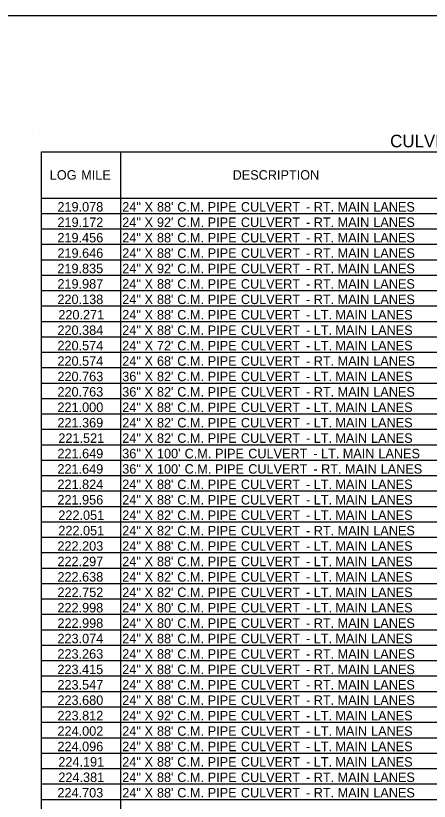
# Model space of a CAD drawing. Extents: x 2261867 to 2275370, y -3124789 to -3122260.
# Drawn here: x 2265138.2 to 2265400.1, y -3124272.1 to -3123775.3 of the extents above; entities that cross this region are included whole.
import ezdxf

# ---------------------------------------------------------------- set-up
doc = ezdxf.new("R2010")
doc.units = 0
for name, color, linetype in [('Default', 7, 'Continuous'), ('DSN_DRFT_Named-Boundary', 7, 'Continuous'), ('DSN_QNTY_Annotation', 7, 'Continuous')]:
    doc.layers.add(name, color=color, linetype=linetype)

msp = doc.modelspace()

# ---------------------------------------------------------------- linework, layer by layer
at = {"layer": 'Default'}
msp.add_line((2265148.63, -3123847.74), (2265148.63, -3123847.74), dxfattribs=at)
at = {"layer": 'DSN_DRFT_Named-Boundary'}
msp.add_lwpolyline([(2264290.05, -3124774.39), (2265915.05, -3124774.39), (2265915.05, -3123775.33), (2264290.05, -3123775.33)], close=True, dxfattribs=at)
at = {"layer": 'DSN_QNTY_Annotation'}
for p, q in [((2265154.48, -3123861.39), (2265745.33, -3123861.39)), ((2265154.48, -3124516.11), (2265154.48, -3123861.39)), ((2265154.48, -3124516.11), (2265154.48, -3123861.39)), ((2265204.69, -3124505.38), (2265204.69, -3123861.39)), ((2265154.48, -3123890.64), (2265745.33, -3123890.64)), ((2265204.69, -3124505.38), (2265204.69, -3123890.64)), ((2265154.48, -3123900.39), (2265745.33, -3123900.39)), ((2265154.48, -3123910.14), (2265745.33, -3123910.14)), ((2265154.48, -3123919.89), (2265745.33, -3123919.89)), ((2265154.48, -3123929.64), (2265745.33, -3123929.64)), ((2265154.48, -3123939.39), (2265745.33, -3123939.39)), ((2265154.48, -3123949.14), (2265745.33, -3123949.14)), ((2265154.48, -3123958.89), (2265745.33, -3123958.89)), ((2265154.48, -3123968.64), (2265745.33, -3123968.64)), ((2265154.48, -3123978.39), (2265745.33, -3123978.39)), ((2265154.48, -3123988.14), (2265745.33, -3123988.14)), ((2265154.48, -3123997.89), (2265745.33, -3123997.89)), ((2265154.48, -3124007.64), (2265745.33, -3124007.64)), ((2265154.48, -3124017.39), (2265745.33, -3124017.39)), ((2265154.48, -3124027.14), (2265745.33, -3124027.14)), ((2265154.48, -3124036.89), (2265745.33, -3124036.89)), ((2265154.48, -3124046.64), (2265745.33, -3124046.64)), ((2265154.48, -3124056.39), (2265745.33, -3124056.39)), ((2265154.48, -3124066.14), (2265745.33, -3124066.14)), ((2265154.48, -3124075.89), (2265745.33, -3124075.89)), ((2265154.48, -3124085.64), (2265745.33, -3124085.64)), ((2265154.48, -3124095.39), (2265745.33, -3124095.39)), ((2265154.48, -3124105.14), (2265745.33, -3124105.14)), ((2265154.48, -3124114.89), (2265745.33, -3124114.89)), ((2265154.48, -3124124.64), (2265745.33, -3124124.64)), ((2265154.48, -3124134.39), (2265745.33, -3124134.39)), ((2265154.48, -3124144.14), (2265745.33, -3124144.14)), ((2265154.48, -3124153.89), (2265745.33, -3124153.89)), ((2265154.48, -3124163.64), (2265745.33, -3124163.64)), ((2265154.48, -3124173.39), (2265745.33, -3124173.39)), ((2265154.48, -3124183.14), (2265745.33, -3124183.14)), ((2265154.48, -3124192.89), (2265745.33, -3124192.89)), ((2265154.48, -3124202.64), (2265745.33, -3124202.64)), ((2265154.48, -3124212.39), (2265745.33, -3124212.39)), ((2265154.48, -3124222.14), (2265745.33, -3124222.14)), ((2265154.48, -3124231.89), (2265745.33, -3124231.89)), ((2265154.48, -3124241.64), (2265745.33, -3124241.64)), ((2265154.48, -3124251.39), (2265745.33, -3124251.39)), ((2265154.48, -3124261.14), (2265745.33, -3124261.14)), ((2265154.48, -3124270.89), (2265745.33, -3124270.89))]:
    msp.add_line(p, q, dxfattribs=at)

# ---------------------------------------------------------------- texts
for s, height, p in [('CULVERT', 8, (2265375.32, -3123858.57)), ('LOG', 6, (2265159.79, -3123879.02)), (' MILE', 6, (2265177.44, -3123879.02)), ('DESCRIPTION', 6, (2265275.58, -3123879.02)), ('219.078', 6, (2265164.63, -3123899.19)), ('24"', 6, (2265205.67, -3123899.19)), (' X', 6, (2265217.57, -3123899.19)), (" 88'", 6, (2265225.44, -3123899.19)), (' C.M.', 6, (2265238.29, -3123899.19)), (' PIPE', 6, (2265257.58, -3123899.19)), (' CULVERT', 6, (2265278.57, -3123899.19)), (' -', 6, (2265319.86, -3123899.19)), (' RT.', 6, (2265324.71, -3123899.19)), (' MAIN', 6, (2265339.82, -3123899.19)), (' LANES', 6, (2265362.42, -3123899.19)), ('219.172', 6, (2265164.66, -3123908.94)), ('24"', 6, (2265205.67, -3123908.94)), (' X', 6, (2265217.57, -3123908.94)), (" 92'", 6, (2265225.44, -3123908.94)), (' C.M.', 6, (2265238.29, -3123908.94)), (' PIPE', 6, (2265257.58, -3123908.94)), (' CULVERT', 6, (2265278.57, -3123908.94)), (' -', 6, (2265319.86, -3123908.94)), (' RT.', 6, (2265324.71, -3123908.94)), (' MAIN', 6, (2265339.82, -3123908.94)), (' LANES', 6, (2265362.42, -3123908.94)), ('219.456', 6, (2265164.63, -3123918.69)), ('24"', 6, (2265205.67, -3123918.69)), (' X', 6, (2265217.57, -3123918.69)), (" 88'", 6, (2265225.44, -3123918.69)), (' C.M.', 6, (2265238.29, -3123918.69)), (' PIPE', 6, (2265257.58, -3123918.69)), (' CULVERT', 6, (2265278.57, -3123918.69)), (' -', 6, (2265319.86, -3123918.69)), (' RT.', 6, (2265324.71, -3123918.69)), (' MAIN', 6, (2265339.82, -3123918.69)), (' LANES', 6, (2265362.42, -3123918.69)), ('219.646', 6, (2265164.63, -3123928.44)), ('24"', 6, (2265205.67, -3123928.44)), (' X', 6, (2265217.57, -3123928.44)), (" 88'", 6, (2265225.44, -3123928.44)), (' C.M.', 6, (2265238.29, -3123928.44)), (' PIPE', 6, (2265257.58, -3123928.44)), (' CULVERT', 6, (2265278.57, -3123928.44)), (' -', 6, (2265319.86, -3123928.44)), (' RT.', 6, (2265324.71, -3123928.44)), (' MAIN', 6, (2265339.82, -3123928.44)), (' LANES', 6, (2265362.42, -3123928.44)), ('219.835', 6, (2265164.61, -3123938.19)), ('24"', 6, (2265205.67, -3123938.19)), (' X', 6, (2265217.57, -3123938.19)), (" 92'", 6, (2265225.44, -3123938.19)), (' C.M.', 6, (2265238.29, -3123938.19)), (' PIPE', 6, (2265257.58, -3123938.19)), (' CULVERT', 6, (2265278.57, -3123938.19)), (' -', 6, (2265319.86, -3123938.19)), (' RT.', 6, (2265324.71, -3123938.19)), (' MAIN', 6, (2265339.82, -3123938.19)), (' LANES', 6, (2265362.42, -3123938.19)), ('219.987', 6, (2265164.63, -3123947.94)), ('24"', 6, (2265205.67, -3123947.94)), (' X', 6, (2265217.57, -3123947.94)), (" 88'", 6, (2265225.44, -3123947.94)), (' C.M.', 6, (2265238.29, -3123947.94)), (' PIPE', 6, (2265257.58, -3123947.94)), (' CULVERT', 6, (2265278.57, -3123947.94)), (' -', 6, (2265319.86, -3123947.94)), (' RT.', 6, (2265324.71, -3123947.94)), (' MAIN', 6, (2265339.82, -3123947.94)), (' LANES', 6, (2265362.42, -3123947.94)), ('220.138', 6, (2265164.63, -3123957.69)), ('24"', 6, (2265205.67, -3123957.69)), (' X', 6, (2265217.57, -3123957.69)), (" 88'", 6, (2265225.44, -3123957.69)), (' C.M.', 6, (2265238.29, -3123957.69)), (' PIPE', 6, (2265257.58, -3123957.69)), (' CULVERT', 6, (2265278.57, -3123957.69)), (' -', 6, (2265319.86, -3123957.69)), (' RT.', 6, (2265324.71, -3123957.69)), (' MAIN', 6, (2265339.82, -3123957.69)), (' LANES', 6, (2265362.42, -3123957.69)), ('220.271', 6, (2265165.21, -3123967.44)), ('24"', 6, (2265205.67, -3123967.44)), (' X', 6, (2265217.57, -3123967.44)), (" 88'", 6, (2265225.44, -3123967.44)), (' C.M.', 6, (2265238.29, -3123967.44)), (' PIPE', 6, (2265257.58, -3123967.44)), (' CULVERT', 6, (2265278.57, -3123967.44)), (' -', 6, (2265319.86, -3123967.44)), (' LT.', 6, (2265324.71, -3123967.44)), (' MAIN', 6, (2265338.42, -3123967.44)), (' LANES', 6, (2265361.02, -3123967.44)), ('220.384', 6, (2265164.64, -3123977.19)), ('24"', 6, (2265205.67, -3123977.19)), (" 88'", 6, (2265225.44, -3123977.19)), (' C.M.', 6, (2265238.29, -3123977.19)), (' CULVERT', 6, (2265278.57, -3123977.19)), (' LANES', 6, (2265361.02, -3123977.19)), (' X', 6, (2265217.57, -3123977.19)), (' PIPE', 6, (2265257.58, -3123977.19)), (' -', 6, (2265319.86, -3123977.19)), (' LT.', 6, (2265324.71, -3123977.19)), (' MAIN', 6, (2265338.42, -3123977.19)), ('220.574', 6, (2265164.64, -3123986.94)), ('24"', 6, (2265205.67, -3123986.94)), (' X', 6, (2265217.57, -3123986.94)), (" 72'", 6, (2265225.44, -3123986.94)), (' C.M.', 6, (2265238.29, -3123986.94)), (' PIPE', 6, (2265257.58, -3123986.94)), (' CULVERT', 6, (2265278.57, -3123986.94)), (' LT.', 6, (2265324.71, -3123986.94)), (' MAIN', 6, (2265338.42, -3123986.94)), (' LANES', 6, (2265361.02, -3123986.94)), (' -', 6, (2265319.86, -3123986.94)), ('220.574', 6, (2265164.64, -3123996.69)), ('24"', 6, (2265205.67, -3123996.69)), (' X', 6, (2265217.57, -3123996.69)), (" 68'", 6, (2265225.44, -3123996.69)), (' C.M.', 6, (2265238.29, -3123996.69)), (' PIPE', 6, (2265257.58, -3123996.69)), (' CULVERT', 6, (2265278.57, -3123996.69)), (' RT.', 6, (2265324.71, -3123996.69)), (' MAIN', 6, (2265339.82, -3123996.69)), (' LANES', 6, (2265362.42, -3123996.69)), (' -', 6, (2265319.86, -3123996.69)), ('220.763', 6, (2265164.63, -3124006.44)), ('36"', 6, (2265205.67, -3124006.44)), (' X', 6, (2265217.57, -3124006.44)), (" 82'", 6, (2265225.44, -3124006.44)), (' C.M.', 6, (2265238.29, -3124006.44)), (' PIPE', 6, (2265257.58, -3124006.44)), (' CULVERT', 6, (2265278.57, -3124006.44)), (' LT.', 6, (2265324.71, -3124006.44)), (' MAIN', 6, (2265338.42, -3124006.44)), (' LANES', 6, (2265361.02, -3124006.44)), (' -', 6, (2265319.86, -3124006.44)), ('220.763', 6, (2265164.63, -3124016.19)), ('36"', 6, (2265205.67, -3124016.19)), (' X', 6, (2265217.57, -3124016.19)), (" 82'", 6, (2265225.44, -3124016.19)), (' C.M.', 6, (2265238.29, -3124016.19)), (' PIPE', 6, (2265257.58, -3124016.19)), (' CULVERT', 6, (2265278.57, -3124016.19)), (' RT.', 6, (2265324.71, -3124016.19)), (' MAIN', 6, (2265339.82, -3124016.19)), (' LANES', 6, (2265362.42, -3124016.19)), (' -', 6, (2265319.86, -3124016.19)), ('221.000', 6, (2265164.64, -3124025.94)), ('24"', 6, (2265205.67, -3124025.94)), (' X', 6, (2265217.57, -3124025.94)), (" 88'", 6, (2265225.44, -3124025.94)), (' C.M.', 6, (2265238.29, -3124025.94)), (' PIPE', 6, (2265257.58, -3124025.94)), (' CULVERT', 6, (2265278.57, -3124025.94)), (' LT.', 6, (2265324.71, -3124025.94)), (' MAIN', 6, (2265338.42, -3124025.94)), (' LANES', 6, (2265361.02, -3124025.94)), (' -', 6, (2265319.86, -3124025.94)), ('221.369', 6, (2265164.63, -3124035.69)), ('24"', 6, (2265205.67, -3124035.69)), (' X', 6, (2265217.57, -3124035.69)), (" 82'", 6, (2265225.44, -3124035.69)), (' C.M.', 6, (2265238.29, -3124035.69)), (' PIPE', 6, (2265257.58, -3124035.69)), (' CULVERT', 6, (2265278.57, -3124035.69)), (' LT.', 6, (2265324.71, -3124035.69)), (' MAIN', 6, (2265338.42, -3124035.69)), (' LANES', 6, (2265361.02, -3124035.69)), (' -', 6, (2265319.86, -3124035.69)), ('221.521', 6, (2265165.21, -3124045.44)), ('24"', 6, (2265205.67, -3124045.44)), (' X', 6, (2265217.57, -3124045.44)), (" 82'", 6, (2265225.44, -3124045.44)), (' C.M.', 6, (2265238.29, -3124045.44)), (' PIPE', 6, (2265257.58, -3124045.44)), (' CULVERT', 6, (2265278.57, -3124045.44)), (' LT.', 6, (2265324.71, -3124045.44)), (' MAIN', 6, (2265338.42, -3124045.44)), (' LANES', 6, (2265361.02, -3124045.44)), (' -', 6, (2265319.86, -3124045.44)), ('221.649', 6, (2265164.63, -3124055.19)), ('36"', 6, (2265205.67, -3124055.19)), (' X', 6, (2265217.57, -3124055.19)), (" 100'", 6, (2265225.44, -3124055.19)), (' C.M.', 6, (2265242.95, -3124055.19)), (' PIPE', 6, (2265262.24, -3124055.19)), (' CULVERT', 6, (2265283.23, -3124055.19)), (' LT.', 6, (2265329.37, -3124055.19)), (' MAIN', 6, (2265343.08, -3124055.19)), (' LANES', 6, (2265365.68, -3124055.19)), (' -', 6, (2265324.52, -3124055.19)), ('221.649', 6, (2265164.63, -3124064.94)), ('36"', 6, (2265205.67, -3124064.94)), (' X', 6, (2265217.57, -3124064.94)), (" 100'", 6, (2265225.44, -3124064.94)), (' C.M.', 6, (2265242.95, -3124064.94)), (' PIPE', 6, (2265262.24, -3124064.94)), (' CULVERT', 6, (2265283.23, -3124064.94)), (' RT.', 6, (2265329.37, -3124064.94)), (' MAIN', 6, (2265344.48, -3124064.94)), (' LANES', 6, (2265367.08, -3124064.94)), (' -', 6, (2265324.52, -3124064.94)), ('221.824', 6, (2265164.64, -3124074.69)), ('24"', 6, (2265205.67, -3124074.69)), (' X', 6, (2265217.57, -3124074.69)), (" 88'", 6, (2265225.44, -3124074.69)), (' C.M.', 6, (2265238.29, -3124074.69)), (' PIPE', 6, (2265257.58, -3124074.69)), (' CULVERT', 6, (2265278.57, -3124074.69)), (' LT.', 6, (2265324.71, -3124074.69)), (' MAIN', 6, (2265338.42, -3124074.69)), (' LANES', 6, (2265361.02, -3124074.69)), (' -', 6, (2265319.86, -3124074.69)), ('221.956', 6, (2265164.63, -3124084.44)), ('24"', 6, (2265205.67, -3124084.44)), (' X', 6, (2265217.57, -3124084.44)), (" 88'", 6, (2265225.44, -3124084.44)), (' C.M.', 6, (2265238.29, -3124084.44)), (' PIPE', 6, (2265257.58, -3124084.44)), (' CULVERT', 6, (2265278.57, -3124084.44)), (' LT.', 6, (2265324.71, -3124084.44)), (' MAIN', 6, (2265338.42, -3124084.44)), (' LANES', 6, (2265361.02, -3124084.44)), (' -', 6, (2265319.86, -3124084.44)), ('222.051', 6, (2265165.21, -3124094.19)), ('24"', 6, (2265205.67, -3124094.19)), (' X', 6, (2265217.57, -3124094.19)), (" 82'", 6, (2265225.44, -3124094.19)), (' C.M.', 6, (2265238.29, -3124094.19)), (' PIPE', 6, (2265257.58, -3124094.19)), (' CULVERT', 6, (2265278.57, -3124094.19)), (' LT.', 6, (2265324.71, -3124094.19)), (' MAIN', 6, (2265338.42, -3124094.19)), (' LANES', 6, (2265361.02, -3124094.19)), (' -', 6, (2265319.86, -3124094.19)), ('222.051', 6, (2265165.21, -3124103.94)), ('24"', 6, (2265205.67, -3124103.94)), (' X', 6, (2265217.57, -3124103.94)), (" 82'", 6, (2265225.44, -3124103.94)), (' C.M.', 6, (2265238.29, -3124103.94)), (' PIPE', 6, (2265257.58, -3124103.94)), (' CULVERT', 6, (2265278.57, -3124103.94)), (' RT.', 6, (2265324.71, -3124103.94)), (' MAIN', 6, (2265339.82, -3124103.94)), (' LANES', 6, (2265362.42, -3124103.94)), (' -', 6, (2265319.86, -3124103.94)), ('222.203', 6, (2265164.63, -3124113.69)), ('24"', 6, (2265205.67, -3124113.69)), (' X', 6, (2265217.57, -3124113.69)), (" 88'", 6, (2265225.44, -3124113.69)), (' C.M.', 6, (2265238.29, -3124113.69)), (' PIPE', 6, (2265257.58, -3124113.69)), (' CULVERT', 6, (2265278.57, -3124113.69)), (' LT.', 6, (2265324.71, -3124113.69)), (' MAIN', 6, (2265338.42, -3124113.69)), (' LANES', 6, (2265361.02, -3124113.69)), (' -', 6, (2265319.86, -3124113.69)), ('222.297', 6, (2265164.63, -3124123.44)), ('24"', 6, (2265205.67, -3124123.44)), (' X', 6, (2265217.57, -3124123.44)), (" 88'", 6, (2265225.44, -3124123.44)), (' C.M.', 6, (2265238.29, -3124123.44)), (' PIPE', 6, (2265257.58, -3124123.44)), (' CULVERT', 6, (2265278.57, -3124123.44)), (' LT.', 6, (2265324.71, -3124123.44)), (' MAIN', 6, (2265338.42, -3124123.44)), (' LANES', 6, (2265361.02, -3124123.44)), (' -', 6, (2265319.86, -3124123.44)), ('222.638', 6, (2265164.63, -3124133.19)), ('24"', 6, (2265205.67, -3124133.19)), (' X', 6, (2265217.57, -3124133.19)), (" 82'", 6, (2265225.44, -3124133.19)), (' C.M.', 6, (2265238.29, -3124133.19)), (' PIPE', 6, (2265257.58, -3124133.19)), (' CULVERT', 6, (2265278.57, -3124133.19)), (' LT.', 6, (2265324.71, -3124133.19)), (' MAIN', 6, (2265338.42, -3124133.19)), (' LANES', 6, (2265361.02, -3124133.19)), (' -', 6, (2265319.86, -3124133.19)), ('222.752', 6, (2265164.66, -3124142.94)), ('24"', 6, (2265205.67, -3124142.94)), (' X', 6, (2265217.57, -3124142.94)), (" 82'", 6, (2265225.44, -3124142.94)), (' C.M.', 6, (2265238.29, -3124142.94)), (' PIPE', 6, (2265257.58, -3124142.94)), (' CULVERT', 6, (2265278.57, -3124142.94)), (' LT.', 6, (2265324.71, -3124142.94)), (' MAIN', 6, (2265338.42, -3124142.94)), (' LANES', 6, (2265361.02, -3124142.94)), (' -', 6, (2265319.86, -3124142.94)), ('222.998', 6, (2265164.63, -3124152.69)), ('24"', 6, (2265205.67, -3124152.69)), (' X', 6, (2265217.57, -3124152.69)), (" 80'", 6, (2265225.44, -3124152.69)), (' C.M.', 6, (2265238.29, -3124152.69)), (' PIPE', 6, (2265257.58, -3124152.69)), (' CULVERT', 6, (2265278.57, -3124152.69)), (' LT.', 6, (2265324.71, -3124152.69)), (' MAIN', 6, (2265338.42, -3124152.69)), (' LANES', 6, (2265361.02, -3124152.69)), (' -', 6, (2265319.86, -3124152.69)), ('222.998', 6, (2265164.63, -3124162.44)), ('24"', 6, (2265205.67, -3124162.44)), (' X', 6, (2265217.57, -3124162.44)), (" 80'", 6, (2265225.44, -3124162.44)), (' C.M.', 6, (2265238.29, -3124162.44)), (' PIPE', 6, (2265257.58, -3124162.44)), (' CULVERT', 6, (2265278.57, -3124162.44)), (' -', 6, (2265319.86, -3124162.44)), (' RT.', 6, (2265324.71, -3124162.44)), (' MAIN', 6, (2265339.82, -3124162.44)), (' LANES', 6, (2265362.42, -3124162.44)), ('223.074', 6, (2265164.64, -3124172.19)), ('24"', 6, (2265205.67, -3124172.19)), (' X', 6, (2265217.57, -3124172.19)), (" 88'", 6, (2265225.44, -3124172.19)), (' C.M.', 6, (2265238.29, -3124172.19)), (' PIPE', 6, (2265257.58, -3124172.19)), (' CULVERT', 6, (2265278.57, -3124172.19)), (' -', 6, (2265319.86, -3124172.19)), (' LT.', 6, (2265324.71, -3124172.19)), (' MAIN', 6, (2265338.42, -3124172.19)), (' LANES', 6, (2265361.02, -3124172.19)), ('223.263', 6, (2265164.63, -3124181.94)), ('24"', 6, (2265205.67, -3124181.94)), (' X', 6, (2265217.57, -3124181.94)), (" 88'", 6, (2265225.44, -3124181.94)), (' C.M.', 6, (2265238.29, -3124181.94)), (' PIPE', 6, (2265257.58, -3124181.94)), (' CULVERT', 6, (2265278.57, -3124181.94)), (' -', 6, (2265319.86, -3124181.94)), (' RT.', 6, (2265324.71, -3124181.94)), (' MAIN', 6, (2265339.82, -3124181.94)), (' LANES', 6, (2265362.42, -3124181.94)), ('223.415', 6, (2265164.61, -3124191.69)), ('24"', 6, (2265205.67, -3124191.69)), (' X', 6, (2265217.57, -3124191.69)), (" 88'", 6, (2265225.44, -3124191.69)), (' C.M.', 6, (2265238.29, -3124191.69)), (' PIPE', 6, (2265257.58, -3124191.69)), (' CULVERT', 6, (2265278.57, -3124191.69)), (' -', 6, (2265319.86, -3124191.69)), (' RT.', 6, (2265324.71, -3124191.69)), (' MAIN', 6, (2265339.82, -3124191.69)), (' LANES', 6, (2265362.42, -3124191.69)), ('223.547', 6, (2265164.63, -3124201.44)), ('24"', 6, (2265205.67, -3124201.44)), (' X', 6, (2265217.57, -3124201.44)), (" 88'", 6, (2265225.44, -3124201.44)), (' C.M.', 6, (2265238.29, -3124201.44)), (' PIPE', 6, (2265257.58, -3124201.44)), (' CULVERT', 6, (2265278.57, -3124201.44)), (' -', 6, (2265319.86, -3124201.44)), (' RT.', 6, (2265324.71, -3124201.44)), (' MAIN', 6, (2265339.82, -3124201.44)), (' LANES', 6, (2265362.42, -3124201.44)), ('223.680', 6, (2265164.64, -3124211.19)), ('24"', 6, (2265205.67, -3124211.19)), (' X', 6, (2265217.57, -3124211.19)), (" 88'", 6, (2265225.44, -3124211.19)), (' C.M.', 6, (2265238.29, -3124211.19)), (' PIPE', 6, (2265257.58, -3124211.19)), (' CULVERT', 6, (2265278.57, -3124211.19)), (' -', 6, (2265319.86, -3124211.19)), (' RT.', 6, (2265324.71, -3124211.19)), (' MAIN', 6, (2265339.82, -3124211.19)), (' LANES', 6, (2265362.42, -3124211.19)), ('223.812', 6, (2265164.66, -3124220.94)), ('24"', 6, (2265205.67, -3124220.94)), (' X', 6, (2265217.57, -3124220.94)), (" 92'", 6, (2265225.44, -3124220.94)), (' C.M.', 6, (2265238.29, -3124220.94)), (' PIPE', 6, (2265257.58, -3124220.94)), (' CULVERT', 6, (2265278.57, -3124220.94)), (' -', 6, (2265319.86, -3124220.94)), (' LT.', 6, (2265324.71, -3124220.94)), (' MAIN', 6, (2265338.42, -3124220.94)), (' LANES', 6, (2265361.02, -3124220.94)), ('224.002', 6, (2265164.66, -3124230.69)), ('24"', 6, (2265205.67, -3124230.69)), (' X', 6, (2265217.57, -3124230.69)), (" 88'", 6, (2265225.44, -3124230.69)), (' C.M.', 6, (2265238.29, -3124230.69)), (' PIPE', 6, (2265257.58, -3124230.69)), (' CULVERT', 6, (2265278.57, -3124230.69)), (' -', 6, (2265319.86, -3124230.69)), (' LT.', 6, (2265324.71, -3124230.69)), (' MAIN', 6, (2265338.42, -3124230.69)), (' LANES', 6, (2265361.02, -3124230.69)), ('224.096', 6, (2265164.63, -3124240.44)), ('24"', 6, (2265205.67, -3124240.44)), (' X', 6, (2265217.57, -3124240.44)), (" 88'", 6, (2265225.44, -3124240.44)), (' C.M.', 6, (2265238.29, -3124240.44)), (' PIPE', 6, (2265257.58, -3124240.44)), (' CULVERT', 6, (2265278.57, -3124240.44)), (' LT.', 6, (2265324.71, -3124240.44)), (' MAIN', 6, (2265338.42, -3124240.44)), (' LANES', 6, (2265361.02, -3124240.44)), (' -', 6, (2265319.86, -3124240.44)), ('224.191', 6, (2265165.21, -3124250.19)), ('24"', 6, (2265205.67, -3124250.19)), (' X', 6, (2265217.57, -3124250.19)), (" 88'", 6, (2265225.44, -3124250.19)), (' C.M.', 6, (2265238.29, -3124250.19)), (' PIPE', 6, (2265257.58, -3124250.19)), (' CULVERT', 6, (2265278.57, -3124250.19)), (' LT.', 6, (2265324.71, -3124250.19)), (' MAIN', 6, (2265338.42, -3124250.19)), (' LANES', 6, (2265361.02, -3124250.19)), (' -', 6, (2265319.86, -3124250.19)), ('224.381', 6, (2265165.21, -3124259.94)), ('24"', 6, (2265205.67, -3124259.94)), (' X', 6, (2265217.57, -3124259.94)), (" 88'", 6, (2265225.44, -3124259.94)), (' C.M.', 6, (2265238.29, -3124259.94)), (' PIPE', 6, (2265257.58, -3124259.94)), (' CULVERT', 6, (2265278.57, -3124259.94)), (' RT.', 6, (2265324.71, -3124259.94)), (' MAIN', 6, (2265339.82, -3124259.94)), (' LANES', 6, (2265362.42, -3124259.94)), (' -', 6, (2265319.86, -3124259.94)), ('224.703', 6, (2265164.63, -3124269.69)), ('24"', 6, (2265205.67, -3124269.69)), (' X', 6, (2265217.57, -3124269.69)), (" 88'", 6, (2265225.44, -3124269.69)), (' C.M.', 6, (2265238.29, -3124269.69)), (' PIPE', 6, (2265257.58, -3124269.69)), (' CULVERT', 6, (2265278.57, -3124269.69)), (' RT.', 6, (2265324.71, -3124269.69)), (' MAIN', 6, (2265339.82, -3124269.69)), (' LANES', 6, (2265362.42, -3124269.69)), (' -', 6, (2265319.86, -3124269.69))]:
    msp.add_text(s, height=height, dxfattribs=at).set_placement(p)

doc.saveas('drawing.dxf')
